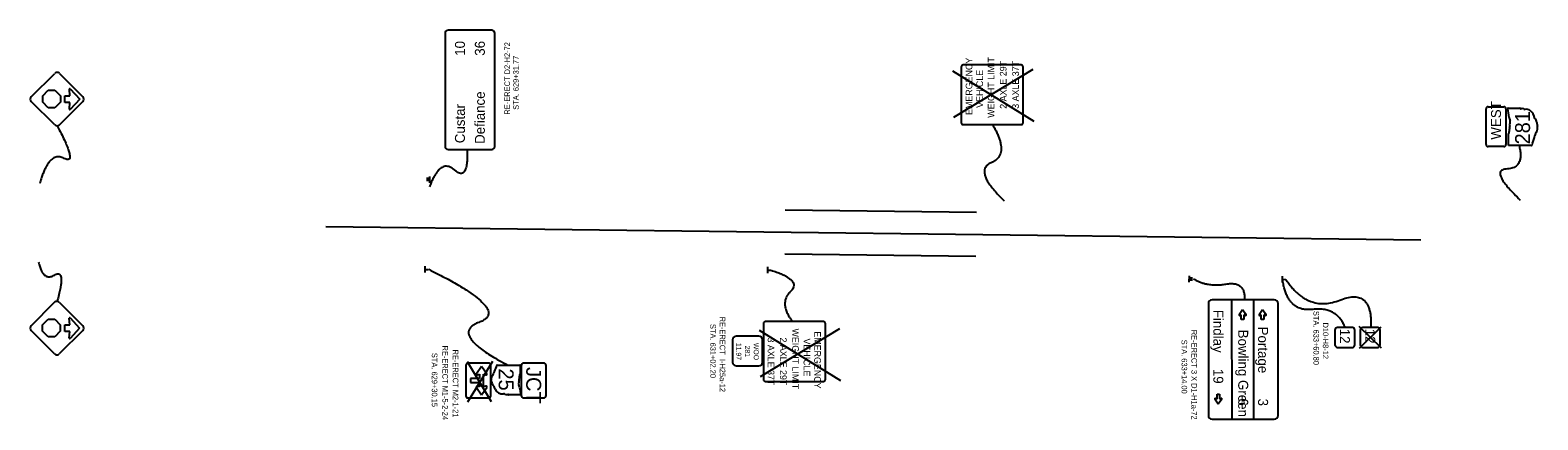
# Model space of a CAD drawing. Extents: x 162802 to 163560, y 412701 to 412897.
import ezdxf

# ---------------------------------------------------------------- set-up
doc = ezdxf.new("R2010")
doc.units = 0
for name, color, linetype in [('BR_P_Sub_Foot_Object', 7, 'Continuous'), ('PM_X_CL_Dashed', 7, 'Continuous'), ('PV_P_EOP', 7, 'Continuous'), ('SH_Text', 7, 'Continuous'), ('SN_P_Signs', 7, 'Continuous'), ('SN_X_Public', 7, 'Continuous'), ('SN_X_Text', 7, 'Continuous')]:
    doc.layers.add(name, color=color, linetype=linetype)

msp = doc.modelspace()

# ---------------------------------------------------------------- linework, layer by layer
at = {"layer": 'BR_P_Sub_Foot_Object'}
for p, q in [((163431.54, 412770.18), (163431.61, 412773.38)), ((163431.57, 412771.78), (163433.17, 412771.75)), ((163481.27, 412737.13), (163470.03, 412748.04)), ((163470.26, 412737.14), (163481.15, 412747.97))]:
    msp.add_line(p, q, dxfattribs=at)
for points in [[(163457.92, 412746.33), (163457.92, 412738.83)], [(163466.67, 412747.58), (163459.17, 412747.58)], [(163467.92, 412738.83), (163467.92, 412746.33)], [(163459.17, 412737.58), (163466.67, 412737.58)]]:
    msp.add_lwpolyline(points, dxfattribs=at)
for centre, start, end in [((163459.17, 412746.33), 90, 180), ((163466.67, 412746.33), 360, 90), ((163459.17, 412738.83), 180, 270), ((163466.67, 412738.83), 270, 360)]:
    msp.add_arc(centre, 1.25, start, end, dxfattribs=at)
msp.add_open_spline([(163462.98, 412747.58), (163458.95, 412758.16), (163433.97, 412755.14), (163431.57, 412771.78)], degree=2, dxfattribs=at)
at = {"layer": 'PM_X_CL_Dashed'}
msp.add_line((162951.05, 412798.33), (163501.01, 412791.67), dxfattribs=at)
at = {"layer": 'PV_P_EOP'}
for p, q in [((163277.8, 412805.37), (163181.81, 412806.54)), ((163181.54, 412784.54), (163277.54, 412783.38))]:
    msp.add_line(p, q, dxfattribs=at)
at = {"layer": 'SN_P_Signs'}
for p, q in [((162808.79, 412864.02), (162811.55, 412866.84)), ((162808.79, 412860.72), (162808.79, 412864.02)), ((162811.55, 412866.84), (162814.91, 412866.84)), ((162814.91, 412866.84), (162817.68, 412864.02)), ((162817.68, 412864.02), (162817.68, 412860.72)), ((162819.91, 412860.64), (162819.91, 412863.98)), ((162819.91, 412863.98), (162822.41, 412863.98)), ((162822.41, 412863.98), (162822.21, 412867.31)), ((162822.57, 412867.46), (162827.41, 412862.31)), ((162811.55, 412857.9), (162808.79, 412860.72)), ((162814.91, 412857.9), (162811.55, 412857.9)), ((162817.68, 412860.72), (162814.91, 412857.9)), ((162822.41, 412860.64), (162819.91, 412860.64)), ((162822.21, 412857.32), (162822.41, 412860.64)), ((162827.41, 412862.31), (162822.57, 412857.16)), ((163533.81, 412839.48), (163533.81, 412857.48)), ((163534.81, 412858.48), (163542.81, 412858.48)), ((163543.81, 412857.48), (163543.81, 412839.48)), ((163544.86, 412857.8), (163550.82, 412857.8)), ((163545.14, 412839.23), (163545.14, 412844.72)), ((163542.81, 412838.48), (163534.81, 412838.48)), ((163556.72, 412839.05), (163545.34, 412839.05)), ((163003.11, 412821.41), (163001.51, 412821.43)), ((163003.12, 412822.37), (163001.52, 412822.39)), ((163003.13, 412823.49), (163003.1, 412820.29)), ((163003.11, 412821.89), (163003.11, 412821.89)), ((163003.11, 412821.89), (163003.11, 412821.89)), ((163000.92, 412775.19), (163000.98, 412778.39)), ((163000.95, 412776.79), (163002.55, 412776.75)), ((163172.97, 412774.79), (163173.04, 412777.99)), ((163173.01, 412776.39), (163174.61, 412776.36)), ((163384.75, 412770.38), (163384.78, 412773.58)), ((163384.77, 412772.46), (163386.37, 412772.45)), ((163384.77, 412771.98), (163384.77, 412771.98)), ((163384.77, 412771.98), (163384.77, 412771.98)), ((163384.76, 412771.5), (163386.36, 412771.49)), ((163406.21, 412701.47), (163406.15, 412761.47)), ((163417.21, 412701.47), (163417.15, 412761.47)), ((162808.74, 412748.97), (162811.51, 412751.78)), ((162811.51, 412751.78), (162814.87, 412751.78)), ((162814.87, 412751.78), (162817.63, 412748.96)), ((162822.36, 412748.92), (162822.17, 412752.25)), ((162822.53, 412752.41), (162827.36, 412747.26)), ((163409.78, 412754.04), (163411.55, 412756.56)), ((163410.88, 412753.9), (163410.07, 412753.65)), ((163410.88, 412753.89), (163410.88, 412753.9)), ((163410.88, 412751.56), (163410.88, 412753.89)), ((163412.21, 412751.56), (163410.88, 412751.56)), ((163411.55, 412756.56), (163413.31, 412754.04)), ((163411.83, 412753.9), (163411.83, 412753.9)), ((163413.02, 412753.65), (163412.21, 412753.9)), ((163419.79, 412754.04), (163421.56, 412756.56)), ((163420.89, 412753.9), (163420.08, 412753.65)), ((163420.89, 412753.89), (163420.89, 412753.9)), ((163420.89, 412751.56), (163420.89, 412753.89)), ((163422.22, 412751.56), (163420.89, 412751.56)), ((163421.56, 412756.56), (163423.32, 412754.04)), ((163421.83, 412753.9), (163421.83, 412753.9)), ((163423.03, 412753.65), (163422.22, 412753.9)), ((162808.74, 412745.67), (162808.74, 412748.97)), ((162811.51, 412742.85), (162808.74, 412745.67)), ((162814.87, 412742.85), (162811.51, 412742.85)), ((162817.63, 412745.67), (162814.87, 412742.85)), ((162817.63, 412748.96), (162817.63, 412745.67)), ((162819.86, 412745.59), (162819.86, 412748.92)), ((162819.86, 412748.92), (162822.36, 412748.92)), ((162822.36, 412745.59), (162819.86, 412745.59)), ((162822.17, 412742.26), (162822.36, 412745.59)), ((162827.36, 412747.26), (162822.53, 412742.11)), ((163029.25, 412727.99), (163026.68, 412724.32)), ((163031.83, 412724.32), (163029.25, 412727.99)), ((163037.05, 412728.69), (163048.43, 412728.69)), ((163048.63, 412728.55), (163048.63, 412724.15)), ((163028.28, 412721.88), (163023.67, 412721.88)), ((163023.67, 412721.88), (163023.67, 412719.93)), ((163023.67, 412719.93), (163028.28, 412719.93)), ((163027.09, 412723.74), (163028.28, 412724.1)), ((163028.28, 412724.1), (163028.28, 412721.88)), ((163028.28, 412719.93), (163028.28, 412717.71)), ((163030.23, 412717.71), (163030.23, 412724.1)), ((163030.23, 412724.1), (163031.41, 412723.74)), ((163031.83, 412724.32), (163031.83, 412724.32)), ((163026.68, 412717.49), (163029.25, 412713.82)), ((163028.28, 412717.71), (163027.09, 412718.07)), ((163029.25, 412713.82), (163031.83, 412717.49)), ((163031.41, 412718.07), (163030.23, 412717.71)), ((163048.91, 412713.69), (163042.96, 412713.69)), ((163399.33, 412709.04), (163397.57, 412711.56)), ((163397.86, 412711.96), (163398.67, 412711.7)), ((163398.67, 412714.04), (163400, 412714.04)), ((163401.1, 412711.56), (163399.33, 412709.04)), ((163400, 412714.04), (163400, 412711.71)), ((163400, 412711.7), (163400.81, 412711.96)), ((163400, 412711.71), (163400, 412711.7)), ((163399.33, 412709.04), (163399.33, 412709.04))]:
    msp.add_line(p, q, dxfattribs=at)
for points in [[(163010.89, 412895.4), (163010.89, 412838.53)], [(163034.33, 412896.97), (163012.45, 412896.97)], [(163035.89, 412838.53), (163035.89, 412895.4)], [(163270.21, 412878.48), (163270.21, 412850.48)], [(163300.27, 412879.48), (163271.21, 412879.48)], [(163301.27, 412850.48), (163301.27, 412878.48)], [(162803.03, 412863.49), (162814.82, 412875.27)], [(162817.18, 412875.27), (162828.96, 412863.49)], [(162814.82, 412849.35), (162803.03, 412861.13)], [(162828.96, 412861.13), (162817.18, 412849.35)], [(163271.21, 412849.48), (163300.27, 412849.48)], [(163012.45, 412836.97), (163034.33, 412836.97)], [(162802.99, 412748.44), (162814.77, 412760.22)], [(162817.13, 412760.22), (162828.91, 412748.44)], [(163394.33, 412759.6), (163394.33, 412703.35)], [(163427.46, 412761.47), (163396.21, 412761.47)], [(163429.33, 412703.35), (163429.33, 412759.6)], [(163170.87, 412749.52), (163170.87, 412721.52)], [(163200.93, 412750.52), (163171.87, 412750.52)], [(163201.93, 412721.52), (163201.93, 412749.52)], [(163412.21, 412753.89), (163412.21, 412751.56)], [(163422.22, 412753.89), (163422.22, 412751.56)], [(162814.77, 412734.29), (162802.99, 412746.08)], [(162828.91, 412746.08), (162817.13, 412734.29)], [(163168.47, 412743.25), (163157.22, 412743.25)], [(163470.64, 412746.33), (163470.64, 412738.83)], [(163479.39, 412747.58), (163471.89, 412747.58)], [(163480.64, 412738.83), (163480.64, 412746.33)], [(163155.35, 412741.38), (163155.35, 412730.13)], [(163170.35, 412730.13), (163170.35, 412741.38)], [(163471.89, 412737.58), (163479.39, 412737.58)], [(163021.37, 412728.66), (163021.37, 412713.16)], [(163032.87, 412729.66), (163022.37, 412729.66)], [(163033.87, 412713.16), (163033.87, 412728.66)], [(163049.18, 412728.45), (163049.18, 412713.45)], [(163060.43, 412729.7), (163050.43, 412729.7)], [(163061.68, 412713.45), (163061.68, 412728.45)], [(163157.22, 412728.25), (163168.47, 412728.25)], [(163171.87, 412720.52), (163200.93, 412720.52)], [(163022.37, 412712.16), (163032.87, 412712.16)], [(163050.43, 412712.2), (163060.43, 412712.2)], [(163398.67, 412711.71), (163398.67, 412714.04)], [(163396.21, 412701.47), (163427.46, 412701.47)]]:
    msp.add_lwpolyline(points, dxfattribs=at)
for centre, radius, start, end in [((163012.45, 412895.4), 1.56, 90, 180), ((163034.33, 412895.4), 1.56, 0, 90), ((163271.21, 412878.48), 1, 90, 180), ((163300.27, 412878.48), 1, 360, 90), ((162816, 412874.1), 1.67, 45, 135), ((162804.21, 412862.31), 1.67, 135, 225), ((162822.42, 412867.32), 0.208, 43.20699, 183.39083), ((162827.78, 412862.31), 1.67, 315, 45), ((162822.42, 412857.3), 0.208, 176.60917, 316.79301), ((163534.81, 412857.48), 1, 90, 180), ((163542.81, 412857.48), 1, 0, 90), ((162816, 412850.53), 1.67, 225, 315), ((163271.21, 412850.48), 1, 180, 270), ((163300.27, 412850.48), 1, 270, 360), ((163012.45, 412838.53), 1.56, 180, 270), ((163034.33, 412838.53), 1.56, 270, 360), ((163534.81, 412839.48), 1, 180, 270), ((163542.81, 412839.48), 1, 270, 360), ((162815.95, 412759.04), 1.67, 45, 135), ((163396.21, 412759.6), 1.88, 90, 180), ((163427.46, 412759.6), 1.88, 360, 90), ((162822.37, 412752.26), 0.208, 43.20699, 183.39083), ((163171.87, 412749.52), 1, 90, 180), ((163200.93, 412749.52), 1, 360, 90), ((163409.99, 412753.89), 0.259, 144.92075, 287.6378), ((163413.1, 412753.89), 0.259, 252.3622, 35.07924), ((163420, 412753.89), 0.259, 144.92075, 287.6378), ((163423.11, 412753.89), 0.259, 252.3622, 35.07924), ((162804.16, 412747.26), 1.67, 135, 225), ((162822.37, 412742.25), 0.208, 176.60917, 316.79301), ((162827.73, 412747.26), 1.67, 315, 45), ((163157.22, 412741.38), 1.88, 90, 180), ((163168.47, 412741.38), 1.88, 360, 90), ((163471.89, 412746.33), 1.25, 90, 180), ((163479.39, 412746.33), 1.25, 360, 90), ((162815.95, 412735.47), 1.67, 225, 315), ((163471.89, 412738.83), 1.25, 180, 270), ((163479.39, 412738.83), 1.25, 270, 360), ((163022.37, 412728.66), 1, 90, 180), ((163032.87, 412728.66), 1, 360, 90), ((163046.62, 412722.13), 11.49, 150.41292, 167.1985), ((163036.39, 412728.22), 0.482, 299.74838, 3.27175), ((163037.03, 412728.52), 0.175, 81.95839, 168.30661), ((163038.19, 412728.49), 1.34, 177.33899, 190.60386), ((163048.46, 412728.52), 0.174, 8.1301, 98.1301), ((163050.43, 412728.45), 1.25, 90, 180), ((163060.43, 412728.45), 1.25, 360, 90), ((163157.22, 412730.13), 1.88, 180, 270), ((163168.47, 412730.13), 1.88, 270, 360), ((163026.98, 412724.1), 0.378, 144.85783, 287.02573), ((163031.52, 412724.1), 0.378, 252.97427, 35.14217), ((163036.34, 412721.67), 2.28, 140.70037, 196.29184), ((163032.4, 412720.35), 1.87, 355.69512, 21.20995), ((163035.48, 412720.18), 1.22, 178.77702, 225.54927), ((163031.94, 412725.55), 3.59, 317.18416, 345.83597), ((163034.38, 412719.08), 0.342, 335.75173, 42.64842), ((163049.01, 412719.16), 1.22, 143.85621, 204.82819), ((163047.2, 412720.46), 1.01, 324.46668, 29.14113), ((163048.52, 412721.18), 0.486, 129.79206, 207.10237), ((163042.24, 412722.55), 6.05, 350.48669, 4.98827), ((163049.95, 412723.11), 1.69, 141.61951, 181.11188), ((163171.87, 412721.52), 1, 180, 270), ((163200.93, 412721.52), 1, 270, 360), ((163022.37, 412713.16), 1, 180, 270), ((163026.98, 412717.71), 0.378, 72.97427, 215.14217), ((163031.52, 412717.71), 0.378, 324.85783, 107.02573), ((163032.87, 412713.16), 1, 270, 360), ((163035.95, 412719.23), 1.29, 192.87319, 233.27711), ((163033.85, 412716.47), 2.18, 4.40312, 52.57675), ((163039.71, 412718.15), 3.98, 202.30889, 278.98584), ((163040.47, 412713.1), 1.13, 46.8065, 96.92959), ((163041.77, 412715.38), 1.55, 250.03296, 293.64957), ((163042.52, 412713.73), 0.258, 17.94398, 120.33697), ((163042.93, 412713.87), 0.179, 199.60381, 277.73413), ((163045.15, 412717.01), 3.2, 7.34618, 30.76885), ((163064.15, 412719.04), 15.91, 185.84447, 198.90645), ((163048.94, 412713.86), 0.167, 261.86209, 7.738), ((163050.43, 412713.45), 1.25, 180, 270), ((163060.43, 412713.45), 1.25, 270, 360), ((163397.78, 412711.71), 0.259, 72.3622, 215.07924), ((163400.89, 412711.71), 0.259, 324.92075, 107.6378), ((163396.21, 412703.35), 1.88, 180, 270), ((163427.46, 412703.35), 1.88, 270, 0)]:
    msp.add_arc(centre, radius, start, end, dxfattribs=at)
for centre, major_axis, start_param, end_param in [((163544.84, 412857.59), (0, 0.209), 6.141152, 7.989035), ((163529.62, 412851.12), (0, 19.88), 4.814394, 5.042369), ((163550.84, 412857.57), (0, 0.223), 5.05454, 6.418171), ((163551.25, 412857.75), (0, 0.323), 1.883978, 3.671073), ((163552.01, 412855.69), (0, 1.94), 5.934695, 6.695948), ((163553.31, 412858.55), (0, 1.41), 2.387724, 3.262537), ((163554.07, 412852.23), (0, 4.97), 5.101752, 6.440018), ((163548.62, 412853.65), (0, 4), 1.699011, 2.107814), ((163551.53, 412846.73), (0, 7.56), 1.404758, 1.657858), ((163546.57, 412849.34), (0, 1.26), 0.950623, 2.079405), ((163545.25, 412848.45), (0, 0.608), 3.836095, 5.185415), ((163544.77, 412850.97), (0, 1.52), 4.081561, 5.145723), ((163559.92, 412854.33), (0, 2.72), 1.647645, 2.488434), ((163557.83, 412850.88), (0, 1.61), 4.937069, 5.64225), ((163559.39, 412851.06), (0, 0.428), 1.147584, 2.315152), ((163558.29, 412849.69), (0, 1.52), 4.691044, 5.507374), ((163557.44, 412847.83), (0, 2.85), 4.026481, 4.996735), ((163561.37, 412849.48), (0, 2.34), 1.495662, 1.94098), ((163543.82, 412846.03), (0, 2.11), 4.042523, 4.731795), ((163557.38, 412839.64), (0, 0.603), 0.519207, 1.627899), ((163547.15, 412847.25), (0, 14.36), 4.195997, 4.488961), ((163561.84, 412842.97), (0, 4.49), 0.823519, 1.323587), ((163545.31, 412839.26), (0, 0.217), 1.712693, 3.28349), ((163556.75, 412839.26), (0, 0.219), 3.00124, 4.508301), ((163555.58, 412839.3), (0, 1.67), 4.665946, 4.897461)]:
    msp.add_ellipse(centre, major_axis=major_axis, ratio=0.8, start_param=start_param, end_param=end_param, dxfattribs=at)
at = {"layer": 'SN_X_Public'}
for points in [[(162816.12, 412848.86), (162826.83, 412828.63), (162811.95, 412836.57), (162807.31, 412819.92)], [(163285.93, 412849.48), (163294.87, 412834.44), (163275.92, 412826.4), (163291.79, 412811.26)], [(163022.03, 412836.97), (163022.61, 412820.38), (163008.58, 412833.02), (163003.11, 412818.27)], [(163550.39, 412839.05), (163553.34, 412827.62), (163535.09, 412826.77), (163550.97, 412811.63)], [(162806.68, 412780.43), (162808.89, 412770.53), (162820.7, 412777.35), (162816.05, 412760.71)], [(163002.8, 412776.8), (163044.33, 412756.15), (163012.28, 412744.53), (163042.33, 412728.69)], [(163174.65, 412776.34), (163190.43, 412771.4), (163178.35, 412759.78), (163185.44, 412750.52)], [(163386.82, 412772.07), (163393.68, 412767.77), (163412.91, 412771.05), (163412.53, 412761.47)], [(163433.24, 412771.75), (163444.19, 412754.87), (163476.8, 412767.94), (163475.99, 412747.58)]]:
    msp.add_open_spline(points, degree=2, dxfattribs=at)
at = {"layer": 'SN_X_Text'}
for p, q in [((163265.87, 412876.47), (163306.66, 412851.16)), ((163306.15, 412877.12), (163266.24, 412853.05)), ((163168.75, 412746.23), (163209.54, 412720.92)), ((163209.03, 412746.87), (163169.12, 412722.81)), ((163021.96, 412730.41), (163034, 412710.46)), ((163022.29, 412710.27), (163034.94, 412730.66))]:
    msp.add_line(p, q, dxfattribs=at)

# ---------------------------------------------------------------- texts
at = {"layer": 'BR_P_Sub_Foot_Object'}
for s, height, p in [('STA. 633+60.80', 2.8, (163447.12, 412755.9)), ('D10-H8-12', 2.8, (163451.84, 412750.06)), ('12', 5, (163460.42, 412746.96))]:
    msp.add_text(s, height=height, rotation=270, dxfattribs=at).set_placement(p)
at = {"layer": 'SH_Text'}
for s, rotation, p in [('RE-ERECT D2-H2-72', 90, (163043.53, 412854.54)), ('STA. 629+31.77', 90, (163047.91, 412856.94)), ('RE-ERECT  I-H25a-12', 270, (163148.9, 412753.03)), ('STA. 631+02.20', 270, (163144.1, 412749.36)), ('RE-ERECT 3 X D1-H1a-72', 270, (163385.85, 412746.44)), ('STA. 629+30.15', 270, (163004.26, 412734.82)), ('RE-ERECT M1-5-2-24', 270, (163009.56, 412738.51)), ('RE-ERECT M2-1-21', 270, (163014.81, 412736.5)), ('STA. 633+14.00', 270, (163380.87, 412741.45))]:
    msp.add_text(s, height=2.8, rotation=rotation, dxfattribs=at).set_placement(p)
at = {"layer": 'SN_P_Signs'}
for s, height, rotation, p in [('10', 5, 90, (163020.89, 412884.08)), ('36', 5, 90, (163030.89, 412884.11)), ('EMERGENCY', 3.333, 90, (163275.79, 412854.37)), ('WEIGHT LIMIT', 3.3333, 90, (163286.86, 412852.95)), ('2 AXLE 29T', 3.333, 90, (163292.94, 412857.46)), ('3 AXLE 37T', 3.333, 90, (163299.16, 412857.46)), ('VEHICLE', 3.333, 90, (163281.16, 412857.94)), ('Defiance', 5, 90, (163030.89, 412839.81)), ('Custar', 5, 90, (163020.89, 412840.15)), ('WEST', 5, 90, (163541.31, 412841.96)), ('281', 7.5, 90, (163555.92, 412839.56)), ('Findlay', 5, 270, (163396.83, 412756.47)), ('3 AXLE 37T', 3.333, 270, (163172.98, 412742.54)), ('2 AXLE 29T', 3.333, 270, (163179.2, 412742.54)), ('WEIGHT LIMIT', 3.3333, 270, (163185.28, 412747.05)), ('VEHICLE', 3.333, 270, (163190.99, 412742.06)), ('EMERGENCY', 3.333, 270, (163196.35, 412745.63)), ('Bowling Green', 5, 270, (163409.33, 412746.47)), ('Portage', 5, 270, (163419.33, 412748.01)), ('12', 5, 270, (163473.14, 412746.95)), ('11.97', 2.5, 270, (163157.22, 412739.84)), ('281', 2.5, 270, (163161.6, 412738.52)), ('WOO', 2.5, 270, (163165.97, 412739.83)), ('JCT', 7.5, 270, (163051.68, 412727.69)), ('25', 7.5, 270, (163037.85, 412727)), ('19', 5, 270, (163396.83, 412726.8)), ('6', 5, 270, (163409.33, 412711.96)), ('3', 5, 270, (163419.33, 412711.85))]:
    msp.add_text(s, height=height, rotation=rotation, dxfattribs=at).set_placement(p)

doc.saveas('drawing.dxf')
